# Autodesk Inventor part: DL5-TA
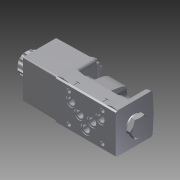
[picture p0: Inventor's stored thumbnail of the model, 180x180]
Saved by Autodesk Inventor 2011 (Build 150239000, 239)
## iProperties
Created: 2012-01
Part Number: DL5-TA
Document SubType Name: Modeling
Designer: khramov
Density: 1 g/cm^3
Author: khramov
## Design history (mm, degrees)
derived "DL5_TA_10N_D12K1.iam"
node "Твердое тело1"
node "0210566_0144453.ipt:1"
node "026986.ipt:1"
node "0119412.ipt:1"
node "190315.ipt:1"
node "0144493.ipt:1"
sketch "3001630001ON.ipt:1"
sketch "0530779_DIN7985.ipt:1"
sketch "0530779_DIN7985.ipt:2"
